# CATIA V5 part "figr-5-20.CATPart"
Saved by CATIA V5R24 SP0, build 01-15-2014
Part number: Part1
Bounding box of the stored display mesh (mm): x -89.73 to 98.105, y -54.237 to 64.207, z 0 to 103
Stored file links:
  D:\KAVITA\CATIA V5-6R2014 Project_ Kavita\CATIA V5-6R2014_partfiles\Partfiles\c05_catia_v5-6r2014_prt\figr-5-20.CATPart
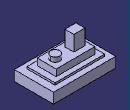
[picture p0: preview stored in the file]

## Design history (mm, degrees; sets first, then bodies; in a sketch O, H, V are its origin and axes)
Body1 (main body)
  Sketch1 on xy-plane, origin (0, 0, 0), H (1, 0, 0), V (0, 1, 0)
    line L1 (-89.7304, 64.2071) -> (98.1053, 64.2071)
    line L2 (98.1053, 64.2071) -> (98.1053, -54.2371)
    line L3 (98.1053, -54.2371) -> (-89.7304, -54.2371)
    line L4 (-89.7304, -54.2371) -> (-89.7304, 64.2071)
    line L5 (-72.4817, 47.8756) -> (77.1251, 47.8756)
    line L6 (77.1251, 47.8756) -> (77.1251, -36.7263)
    line L7 (77.1251, -36.7263) -> (-72.4817, -36.7263)
    line L8 (-72.4817, -36.7263) -> (-72.4817, 47.8756)
    line L9 (-57.1864, 33.5363) -> (59.44, 33.5363)
    line L10 (59.44, 33.5363) -> (59.44, -23.821)
    line L11 (59.44, -23.821) -> (-57.1864, -23.821)
    line L12 (-57.1864, -23.821) -> (-57.1864, 33.5363)
    circle A1 centre (34.1072, 5.3356) radius 13.9353
    line L13 (-44.759, 16.3291) -> (-11.3006, 16.3291)
    line L14 (-11.3006, 16.3291) -> (-11.3006, -10.9156)
    line L15 (-11.3006, -10.9156) -> (-44.759, -10.9156)
    line L16 (-44.759, -10.9156) -> (-44.759, 16.3291)
    horizontal: L1 H, L3 H, L5 H, L7 H, L9 H, L11 H, L13 H, L15 H
    vertical: L4 V, L6 V, L8 V, L10 V, L12 V, L14 V, L16 V
  MultiPad1: profile Sketch1, domains (length 103; length 57; length 0 / length -37; length 31; length 71)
